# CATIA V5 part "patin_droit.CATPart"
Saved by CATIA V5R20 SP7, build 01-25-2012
Part number: patin_droit
Bounding box of the stored display mesh (mm): x 296.558 to 574.226, y -188.302 to 188.302, z -20 to 0
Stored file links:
  U:\IAO\thinkmotion catia2\patin_droit.CATPart
  U:\IAO\thinkmotion catia2\Ass_862_adubourgno.CATProduct
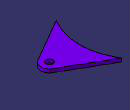
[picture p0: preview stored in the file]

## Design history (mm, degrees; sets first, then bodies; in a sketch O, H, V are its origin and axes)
Set1
  Plane1: linked copy from another document
  Point1 "J": linked copy from another document
  Point2 "M": linked copy from another document
Body1 (main body)
  Sketch1 on Plane1, origin (0, 0, 0), H (1, 0, 0), V (0, 1, 0)
    construction line L1 (350, 0) -> (524.226, 0)
    point P1 (350, 0)
    point P2 (524.226, 0)
    reference projected point E1 (524.226, 0) from Point1
    reference projected point E2 (350, 0) from Point2
    axis line L2 (547.0246, 27.1703) -> (524.226, 0)
    point P3 (547.0246, 27.1703)
    point P4 (524.226, 0)
    reference projected point E3 (524.226, 0) from Point1
    point P5 (524.226, 0)
    point P6 (547.0246, -27.1703)
    construction line L3 (547.0246, -27.1703) -> (524.226, 0)
    arc A1 centre (524.226, 0) radius 50 from (556.3654, -38.3022) to (556.3654, 38.3022) ccw
    point P7 (524.226, 0)
    point P8 (556.3654, -38.3022)
    point P9 (556.3654, 38.3022)
    reference projected point E4 (524.226, 0) from Point1
    line L4 (556.3654, 38.3022) -> (296.5578, 188.3022)
    point P10 (296.5578, 188.3022)
    point P11 (296.5578, -188.3022)
    point P12 (556.3654, -38.3022)
    line L5 (556.3654, -38.3022) -> (296.5578, -188.3022)
    arc A2 centre (1.5285, 0) radius 350 from (296.5578, -188.3022) to (296.5578, 188.3022) ccw
    point P13 (1.5285, 0)
    circle A3 centre (524.226, 0) radius 20
    point P14 (524.226, 0)
    reference projected point E5 (524.226, 0) from Point1
    distance E1 P2 = 0
    distance E2 P1 = 0
    distance E3 P4 = 0
    angle L1 L2 = 130
    distance E4 P7 = 0
    radius A1 = 50
    angle L4 L1 = 150
    length L4 = 300
    radius A2 = 350
    radius A3 = 20
    distance E5 P14 = 0
    symmetry: P4 P5 L1, P3 P6 L1, L2 L3 L1, P10 P11 L1, P9 P12 L1, L4 L5 L1
    coincidence: P8 L3, P9 L2, P13 H, P8 P12
  Pad1: profile Sketch1, direction (0, 0, -1), length 20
